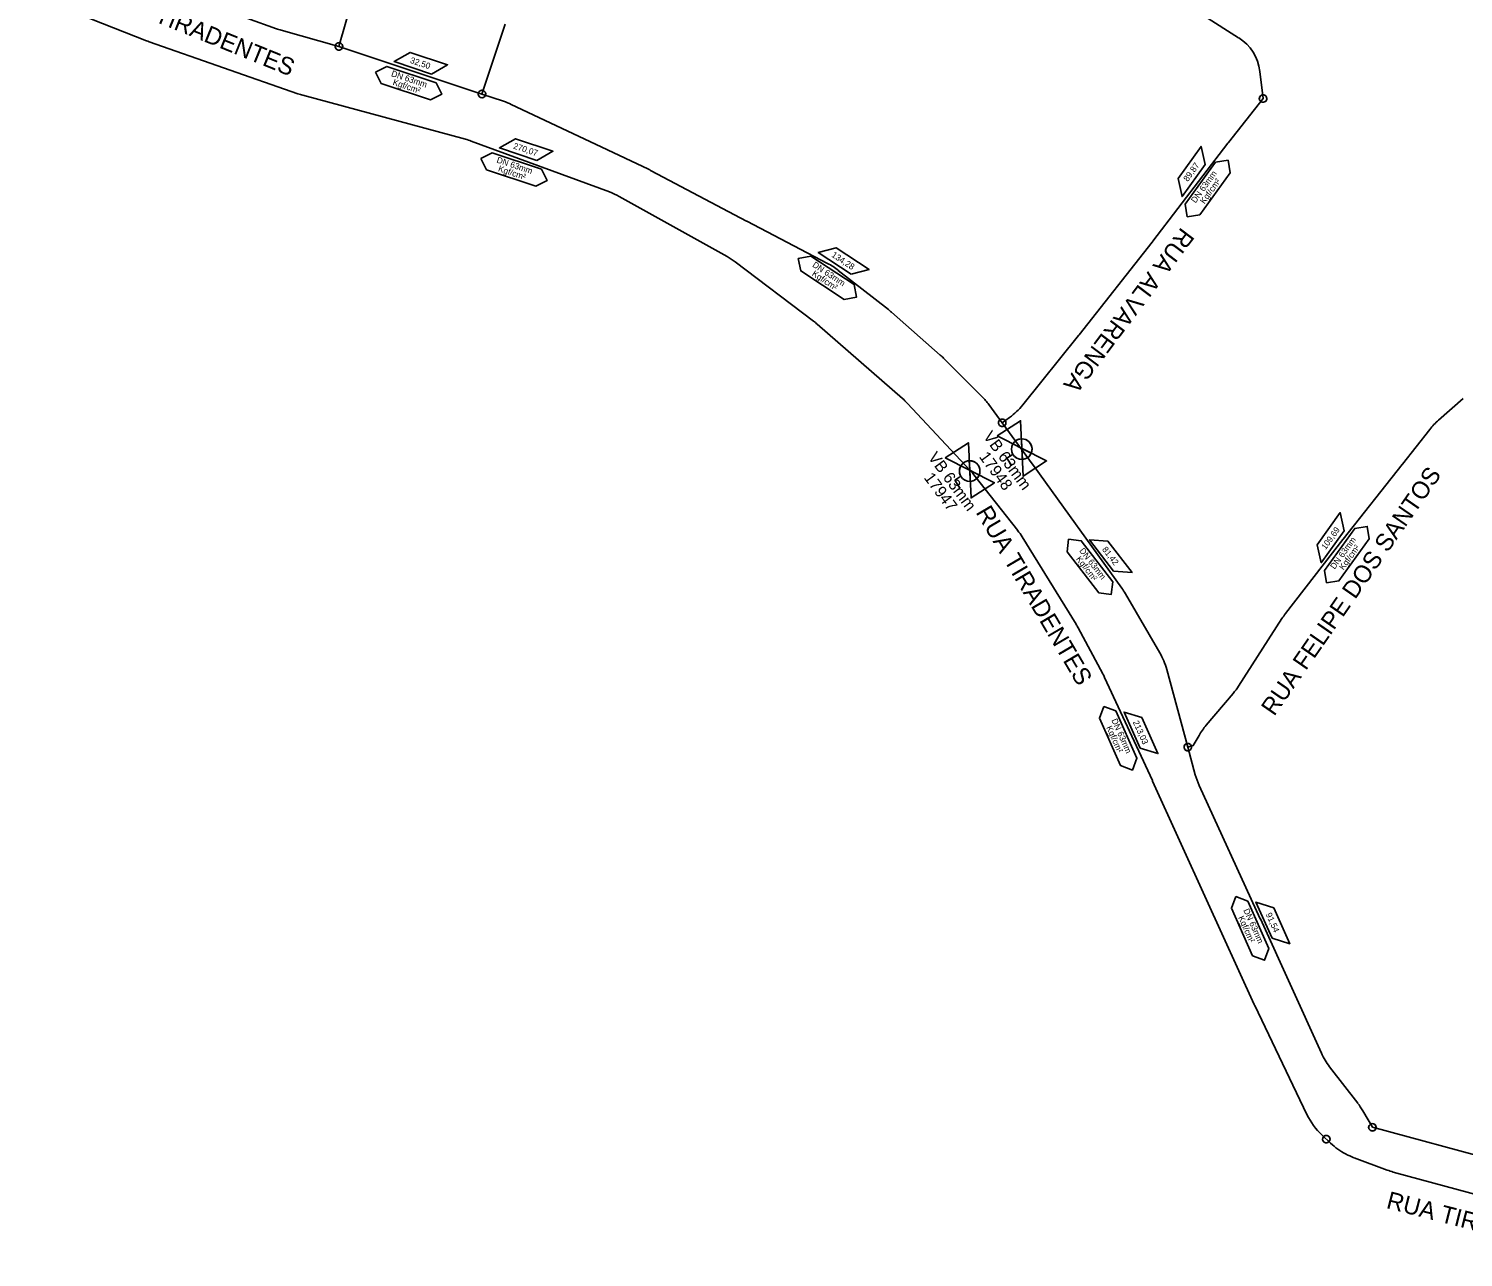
# Model space of a CAD drawing. Extents: x 325899 to 364828, y 7568995 to 7592502.
# Drawn here: x 363258 to 363823, y 7573042 to 7573526 of the extents above; entities that cross this region are included whole.
import ezdxf

# ---------------------------------------------------------------- set-up
doc = ezdxf.new("R2010")
doc.units = 0
for name, color, linetype in [('SIMBOLO', 7, 'Continuous'), ('TEXTO', 7, 'Continuous'), ('TUBO_PEAD_GN_63', 7, 'Continuous'), ('VALVULA_PEAD_63', 7, 'Continuous')]:
    doc.layers.add(name, color=color, linetype=linetype)

# ---------------------------------------------------------------- blocks, each defined once
blk = doc.blocks.new('A$Cbdfb3453_1')
blk.add_lwpolyline([(0.609, 1.387), (-0.609, -1.387), (-1.507, -0.153), (1.507, 0.153)], close=True)
for points in [[(-0.602, -0.061), (0, 0), (0.22, 0.5)], [(0.519, 0.053), (0, 0), (-0.233, -0.53)], [(0.22, 0.5), (0, 0), (0.519, 0.053)], [(-0.233, -0.53), (0, 0), (-0.602, -0.061)]]:
    blk.add_lwpolyline(points)
blk.add_circle((-0.042, 0.001), 0.564)
for start, end in [(62.35405, 186.30109), (250.23755, 5.26822), (5.26822, 62.35405), (186.30109, 250.23755)]:
    blk.add_arc((-0.042, 0.001), 0.564, start, end)
at = {"layer": 'TEXTO'}
for p, q in [((-0.585, 0.789), (-0.977, 0.504)), ((-0.386, 0.515), (-0.585, 0.789))]:
    blk.add_line(p, q, dxfattribs=at)
blk.add_lwpolyline([(0.609, 1.387), (-0.609, -1.387), (-1.507, -0.153), (1.507, 0.153)], close=True, dxfattribs=at)
blk = doc.blocks.new('INTERLIGACAO_1')
at = {"layer": 'SIMBOLO'}
blk.add_circle((0, 0), 0.389, dxfattribs=at)
for start, end in [(0, 180), (180, 0)]:
    blk.add_arc((0, 0), 0.389, start, end, dxfattribs=at)
blk = doc.blocks.new('INTERLIGACAO_10')
at = {"layer": 'SIMBOLO'}
blk.add_circle((0, 0), 0.389, dxfattribs=at)
for start, end in [(0, 180), (180, 0)]:
    blk.add_arc((0, 0), 0.389, start, end, dxfattribs=at)
blk = doc.blocks.new('INTERLIGACAO_24')
at = {"layer": 'SIMBOLO'}
blk.add_circle((0, 0), 0.389, dxfattribs=at)
for start, end in [(0, 180), (180, 0)]:
    blk.add_arc((0, 0), 0.389, start, end, dxfattribs=at)
blk = doc.blocks.new('INTERLIGACAO_25')
at = {"layer": 'SIMBOLO'}
blk.add_circle((0, 0), 0.389, dxfattribs=at)
for start, end in [(0, 180), (180, 0)]:
    blk.add_arc((0, 0), 0.389, start, end, dxfattribs=at)

msp = doc.modelspace()

# ---------------------------------------------------------------- linework, layer by layer
at = {"layer": 'SIMBOLO'}
for points in [[(363416.47, 7573508.54), (363401.7, 7573513.46), (363408.03, 7573517.11), (363422.8, 7573512.2)], [(363458.04, 7573474.47), (363443.26, 7573479.39), (363449.6, 7573483.04), (363464.37, 7573478.13)], [(363721.56, 7573472.85), (363712.46, 7573460.22), (363710.86, 7573467.35), (363719.96, 7573479.99)], [(363581.97, 7573429.6), (363568.97, 7573438.16), (363576.04, 7573440.05), (363589.04, 7573431.49)], [(363776.44, 7573328.43), (363767.34, 7573315.79), (363765.75, 7573322.93), (363774.84, 7573335.57)], [(363685.47, 7573312.5), (363675.95, 7573324.82), (363683.25, 7573324.32), (363692.77, 7573312)], [(363695.94, 7573242.73), (363689.57, 7573256.94), (363696.55, 7573254.74), (363702.91, 7573240.53)], [(363747.98, 7573167.78), (363741.61, 7573181.98), (363748.59, 7573179.78), (363754.95, 7573165.58)]]:
    msp.add_lwpolyline(points, close=True, dxfattribs=at)
for points in [[(363394.36, 7573509.33), (363398.84, 7573511.57), (363418.24, 7573505.1), (363420.48, 7573500.61), (363416, 7573498.37), (363396.6, 7573504.85), (363394.36, 7573509.33)], [(363435.92, 7573475.26), (363440.41, 7573477.5), (363459.81, 7573471.03), (363462.05, 7573466.54), (363457.56, 7573464.3), (363438.16, 7573470.78), (363435.92, 7573475.26)], [(363714.51, 7573452.25), (363713.71, 7573457.2), (363725.68, 7573473.78), (363730.62, 7573474.58), (363731.42, 7573469.64), (363719.45, 7573453.05), (363714.51, 7573452.25)], [(363561.1, 7573435.79), (363566.01, 7573436.79), (363583.08, 7573425.52), (363584.08, 7573420.61), (363579.17, 7573419.61), (363562.1, 7573430.88), (363561.1, 7573435.79)], [(363769.39, 7573307.83), (363768.59, 7573312.78), (363780.56, 7573329.36), (363785.51, 7573330.16), (363786.31, 7573325.22), (363774.34, 7573308.63), (363769.39, 7573307.83)], [(363667.73, 7573325.12), (363672.7, 7573324.48), (363685.2, 7573308.29), (363684.56, 7573303.32), (363679.59, 7573303.96), (363667.09, 7573320.15), (363667.73, 7573325.12)], [(363681.65, 7573259.16), (363686.33, 7573257.37), (363694.68, 7573238.7), (363692.89, 7573234.02), (363688.21, 7573235.8), (363679.86, 7573254.48), (363681.65, 7573259.16)], [(363733.69, 7573184.2), (363738.37, 7573182.41), (363746.72, 7573163.74), (363744.93, 7573159.06), (363740.25, 7573160.85), (363731.9, 7573179.52), (363733.69, 7573184.2)]]:
    msp.add_lwpolyline(points, dxfattribs=at)
at = {"layer": 'TUBO_PEAD_GN_63'}
for p, q in [((363662.92, 7573568.59), (363734.78, 7573522.9)), ((363290.97, 7573549.62), (363355.27, 7573526.44)), ((363257.6, 7573540.02), (363304.08, 7573521.66)), ((363445.56, 7573528.23), (363436.37, 7573500.67)), ((363357.19, 7573525.83), (363379.97, 7573519.46)), ((363305.1, 7573521.28), (363363.79, 7573500.76)), ((363379.97, 7573519.46), (363436.37, 7573500.67)), ((363743.13, 7573509.62), (363744.4, 7573498.89)), ((363365.71, 7573500.17), (363429.81, 7573482.89)), ((363436.37, 7573500.67), (363444.88, 7573497.83)), ((363744.4, 7573498.89), (363730.78, 7573481.59)), ((363447.94, 7573496.6), (363476.62, 7573483.04)), ((363432.16, 7573482.14), (363486.62, 7573462.06)), ((363730.54, 7573481.28), (363700.96, 7573442.59)), ((363503.09, 7573470.44), (363540.62, 7573450.56)), ((363490.48, 7573460.28), (363533.04, 7573436.55)), ((363540.78, 7573450.48), (363572.66, 7573433.86)), ((363700.71, 7573442.28), (363671.86, 7573405.65)), ((363536.24, 7573434.46), (363567.1, 7573411.09)), ((363576.88, 7573431.14), (363596.62, 7573415.69)), ((363597.82, 7573414.7), (363617.11, 7573397.75)), ((363568.57, 7573409.9), (363602.16, 7573380.61)), ((363671.67, 7573405.41), (363649.63, 7573378.06)), ((363618.41, 7573396.54), (363633.54, 7573381.41)), ((363823.37, 7573380.64), (363813.63, 7573372.1)), ((363604.18, 7573378.66), (363628.86, 7573352.23)), ((363636.28, 7573378.2), (363641.55, 7573370.99)), ((363644.46, 7573373.12), (363641.55, 7573370.99)), ((363641.55, 7573370.99), (363653.77, 7573354.29)), ((363810.11, 7573368.38), (363799.38, 7573354.67)), ((363653.88, 7573354.13), (363688.67, 7573305.83)), ((363799.31, 7573354.58), (363776.05, 7573325.12)), ((363630.37, 7573350.48), (363647.63, 7573328.55)), ((363649.42, 7573325.99), (363670.64, 7573291.59)), ((363775.92, 7573324.96), (363753.27, 7573295.8)), ((363690.12, 7573303.6), (363703.65, 7573280.35)), ((363671.46, 7573290.16), (363681.2, 7573272.04)), ((363751.85, 7573293.79), (363734.76, 7573267.19)), ((363706.43, 7573273.72), (363714.72, 7573243.11)), ((363681.93, 7573270.58), (363700.77, 7573229.88)), ((363732.62, 7573264.29), (363722.01, 7573251.76)), ((363714.72, 7573243.11), (363717.67, 7573232.19)), ((363700.86, 7573229.69), (363722.09, 7573182.93)), ((363719.22, 7573227.92), (363743.32, 7573175.44)), ((363722.1, 7573182.89), (363740.9, 7573141.63)), ((363743.36, 7573175.34), (363767.42, 7573122.43)), ((363741.13, 7573141.14), (363761.72, 7573098.2)), ((363770.66, 7573117.04), (363781.72, 7573102.69)), ((363783.71, 7573099.72), (363787.51, 7573093.16)), ((363787.51, 7573093.16), (363863.83, 7573072.58)), ((363767.65, 7573090.09), (363771.04, 7573086.9)), ((363780.27, 7573081.17), (363793.39, 7573076.28)), ((363795.73, 7573075.53), (363893, 7573048.9))]:
    msp.add_line(p, q, dxfattribs=at)
for points in [[(363611.04, 7573870.82), (363531.89, 7573800.71), (363500.05, 7573756.64), (363444.25, 7573678.18), (363416.47, 7573624.72), (363387.61, 7573546.44), (363379.97, 7573519.46)], [(363476.65, 7573483.02), (363476.65, 7573483.02), (363502.02, 7573470.98)], [(363719.15, 7573247.69), (363716.86, 7573243.69), (363714.72, 7573243.11)]]:
    msp.add_lwpolyline(points, dxfattribs=at)
for centre, radius, start, end in [((363314.16, 7573547.18), 27.43, 248.4549, 250.7264), ((363364.58, 7573552.25), 27.43, 250.1808, 254.3858), ((363724.97, 7573507.46), 18.29, 6.7833, 57.5477), ((363372.85, 7573526.66), 27.43, 250.7264, 254.9139), ((363436.21, 7573471.8), 27.43, 64.6856, 71.5652), ((363422.67, 7573456.4), 27.43, 69.7533, 74.9139), ((363464.89, 7573458.24), 27.43, 64.6022, 64.6856), ((363752.33, 7573464.62), 27.43, 141.7833, 142.5978), ((363490.25, 7573446.2), 27.43, 62.0969, 64.6022), ((363477.12, 7573436.32), 27.43, 60.8576, 69.7533), ((363553.46, 7573474.81), 27.43, 242.0969, 242.4635), ((363679.16, 7573459.26), 27.43, 321.7719, 322.5978), ((363519.68, 7573412.59), 27.43, 52.8688, 60.8576), ((363559.98, 7573409.54), 27.43, 51.957, 62.4635), ((363579.72, 7573394.09), 27.43, 48.7055, 51.957), ((363550.54, 7573389.22), 27.43, 48.9165, 52.8688), ((363650.31, 7573422.62), 27.43, 321.1489, 321.7719), ((363599.01, 7573377.14), 27.43, 44.9964, 48.7055), ((363584.13, 7573359.94), 27.43, 43.0444, 48.9165), ((363614.14, 7573362.01), 27.43, 36.1718, 44.9964), ((363628.27, 7573395.26), 27.43, 306.1718, 321.1489), ((363831.71, 7573351.47), 27.43, 131.2326, 141.946), ((363608.82, 7573333.51), 27.43, 38.2066, 43.0444), ((363631.62, 7573338.1), 27.43, 35.7643, 36.1718), ((363777.77, 7573371.58), 27.43, 321.7164, 321.946), ((363626.07, 7573311.58), 27.43, 31.6723, 38.2066), ((363797.59, 7573308.12), 27.43, 141.7164, 142.1533), ((363666.41, 7573289.8), 27.43, 30.2077, 35.7643), ((363774.93, 7573278.96), 27.43, 142.1533, 147.2847), ((363647.3, 7573277.18), 27.43, 28.2406, 31.6723), ((363679.95, 7573266.55), 27.43, 15.1558, 30.2077), ((363657.03, 7573259.06), 27.43, 24.8457, 28.2406), ((363711.68, 7573282.02), 27.43, 319.7472, 327.2847), ((363742.94, 7573234.04), 27.43, 139.7472, 150.1558), ((363675.88, 7573218.35), 27.43, 24.4161, 24.8457), ((363744.15, 7573239.36), 27.43, 195.1558, 204.6606), ((363747.07, 7573194.27), 27.43, 204.4161, 204.4934), ((363718.39, 7573163.99), 27.43, 24.4521, 24.6606), ((363765.87, 7573153), 27.43, 204.4934, 205.6198), ((363792.39, 7573133.78), 27.43, 204.4521, 217.6078), ((363786.46, 7573110.06), 27.43, 205.6198, 226.7262), ((363759.98, 7573085.95), 27.43, 30.1223, 37.6078), ((363789.84, 7573106.87), 27.43, 226.7262, 234.4975), ((363789.84, 7573106.87), 27.43, 234.4975, 249.5714), ((363802.97, 7573101.98), 27.43, 249.5714, 254.6942)]:
    msp.add_arc(centre, radius, start, end, dxfattribs=at)

# ---------------------------------------------------------------- block references
at = {"layer": 'SIMBOLO', "xscale": 3.774920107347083, "yscale": 3.774920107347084, "rotation": 166.3322212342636}
for name, p in [('INTERLIGACAO_1', (363379.97, 7573519.46)), ('INTERLIGACAO_1', (363436.37, 7573500.67)), ('INTERLIGACAO_10', (363744.4, 7573498.89)), ('INTERLIGACAO_1', (363641.55, 7573370.99)), ('INTERLIGACAO_1', (363714.72, 7573243.11)), ('INTERLIGACAO_24', (363787.51, 7573093.16)), ('INTERLIGACAO_25', (363769.35, 7573088.5))]:
    msp.add_blockref(name, p, dxfattribs=at)
at = {"layer": 'VALVULA_PEAD_63', "xscale": 7.199999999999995, "yscale": 7.199999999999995, "rotation": 86.88171380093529}
for p in [(363649.27, 7573360.92), (363628.73, 7573352.27)]:
    msp.add_blockref('A$Cbdfb3453_1', p, dxfattribs=at)

# ---------------------------------------------------------------- texts
for s, p in [('VB 63mm', (363633.84, 7573365.63)), ('VB 63mm', (363612.07, 7573357.38)), ('17948', (363632.21, 7573357.58)), ('17947', (363610.44, 7573349.33))]:
    msp.add_text(s, height=4.572, rotation=306.3217).set_placement(p)
at = {"layer": 'TEXTO'}
for s, height, rotation, p in [('RUA TIRADENTES', 6.858, 337.9272, (363286.58, 7573537.64)), ('32,50', 2.43, 341.658, (363407.83, 7573513)), ('DN 63mm', 2.43, 341.5403, (363400.37, 7573507.77)), ('Kgf/cm²', 2.43, 341.5403, (363400.98, 7573504.35)), ('270,07', 2.43, 341.658, (363448.5, 7573479.22)), ('DN 63mm', 2.43, 341.5403, (363441.94, 7573473.69)), ('Kgf/cm²', 2.43, 341.5403, (363442.55, 7573470.28)), ('89,87', 2.43, 54.3018, (363714.73, 7573465.93)), ('DN 63mm', 2.43, 54.1841, (363717.76, 7573457.47)), ('Kgf/cm²', 2.43, 54.1841, (363721.28, 7573457.14)), ('RUA ALVARENGA', 6.858, 233.0354, (363712.24, 7573448.42)), ('134,28', 2.43, 326.6764, (363573.99, 7573436.65)), ('Kgf/cm²', 2.43, 326.5588, (363566.26, 7573429.23)), ('DN 63mm', 2.43, 326.5588, (363566.44, 7573432.76)), ('RUA FELIPE DOS SANTOS', 6.858, 55.3114, (363748.81, 7573255)), ('RUA TIRADENTES', 6.858, 300.4791, (363630.92, 7573335.74)), ('109,69', 2.43, 54.3018, (363769.07, 7573320.74)), ('DN 63mm', 2.43, 54.1841, (363772.64, 7573313.04)), ('Kgf/cm²', 2.43, 307.6635, (363670.49, 7573317.24)), ('DN 63mm', 2.43, 307.6635, (363671.81, 7573320.52)), ('81,42', 2.43, 307.7812, (363680.78, 7573321.01)), ('Kgf/cm²', 2.43, 54.1841, (363776.16, 7573312.72)), ('Kgf/cm²', 2.43, 294.0915, (363682.48, 7573250.85)), ('DN 63mm', 2.43, 294.0915, (363684.53, 7573253.73)), ('213,03', 2.43, 294.2092, (363692.99, 7573252.96)), ('Kgf/cm²', 2.43, 294.0915, (363734.52, 7573175.9)), ('DN 63mm', 2.43, 294.0915, (363736.57, 7573178.78)), ('91,54', 2.43, 294.2092, (363745.41, 7573177.15)), ('RUA TIRADENTES', 6.858, 345.6564, (363792.67, 7573061.36))]:
    msp.add_text(s, height=height, rotation=rotation, dxfattribs=at).set_placement(p)

doc.saveas('drawing.dxf')
